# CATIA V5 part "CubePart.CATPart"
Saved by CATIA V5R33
Part number: Part1
Bounding box of the stored display mesh (mm): x 0 to 40, y 0 to 30, z 0 to 30
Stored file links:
  C:\Users\william.gallego\Downloads\Cubes\1_Cube--Asm_1_Cube-=Asm_2_Cubes\CubePart.CATPart
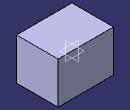
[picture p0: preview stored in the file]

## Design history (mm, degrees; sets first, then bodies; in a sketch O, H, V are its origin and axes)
Body1 (main body)
  Sketch1 on yz-plane, origin (0, 0, 0), H (0, 1, 0), V (0, 0, 1)
    line L1 (0, 0) -> (30, 0)
    line L2 (30, 0) -> (30, 30)
    line L3 (30, 30) -> (0, 30)
    line L4 (0, 30) -> (0, 0)
    horizontal: L1 H, L3 H
    vertical: L2 V, L4 V
  Pad1: profile Sketch1, direction (1, 0, 0), length 40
